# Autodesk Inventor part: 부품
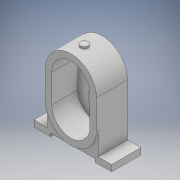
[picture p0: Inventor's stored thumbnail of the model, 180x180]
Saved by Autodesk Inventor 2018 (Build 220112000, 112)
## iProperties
Created: 2021-05
Part Number: 부품
Material: 일반
Document SubType Name: Modeling
Designer: admin
Density: 1 g/cm^3
Appearance: 기본값
Author: admin
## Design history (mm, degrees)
sketch "스케치1"
  geometry: L1 (85.4, 0)-(-85.4, 0) reference; L2 (0, -74.9)-(0, 109.9) reference; L3 (40, 43.5)-(40, -38.5); L4 (40, -38.5)-(61, -38.5); L5 (61, -38.5)-(61, -48.5); L6 (61, -48.5)-(35, -48.5); L7 (35, -48.5)-(35, -43.5); L8 (35, -43.5)-(0, -43.5); L9 (-40, 43.5)-(-40, -38.5); L10 (-40, -38.5)-(-61, -38.5); L11 (-61, -38.5)-(-61, -48.5); L12 (-61, -48.5)-(-35, -48.5); L13 (-35, -48.5)-(-35, -43.5); L14 (-35, -43.5)-(0, -43.5); L15 (40, 43.5)-(-40, 43.5); A1 r 40 centre (0, 43.5) between (40, 43.5) and (-40, 43.5); 1 further point
  constraints: 26 end point, 6 symmetric about line, 5 perpendicular, 2 point on circle, 1 centre point, 1 horizontal, 1 midpoint, 1 point on line, 1 vertical, 1 other
  dimensions: "d0" = 70 distance between parallel lines of L13 L7; "d1" = 10 distance between parallel lines of L6 L4; "d2" = 122 distance between parallel lines of L11 L5; "d4" = 5 distance of L12.end L13.end; "d5" = 80 distance of L3.start L9.start; "d6" = 92 distance between parallel lines of L12 L15
extrude "돌출1" new body sketch "스케치1" stored distance "d7" = 46; taper "d8" = 0 deg
sketch "스케치2"
  geometry: L1 (40, -43.5)-(40, 38.5) reference; L2 (40, 38.5)-(61, 38.5) reference; L3 (61, 38.5)-(61, 48.5) reference; L4 (61, 48.5)-(35, 48.5) reference; L5 (35, 48.5)-(35, 43.5) reference; L6 (35, 43.5)-(-35, 43.5) reference; L7 (-35, 43.5)-(-35, 48.5) reference; L8 (-35, 48.5)-(-61, 48.5) reference; L9 (-61, 48.5)-(-61, 38.5) reference; L10 (-61, 38.5)-(-40, 38.5) reference; L11 (-40, 38.5)-(-40, -43.5) reference; L12 (-85.4, 0)-(85.4, 0) reference; L13 (0, 74.9)-(0, -109.9) reference; L14 (0, 1.5)-(0, -43.5); L15 (26, 1.5)-(26, -43.5); L16 (-26, -43.5)-(-26, 1.5); A1 r 40 centre (0, -43.5) between (-40, -43.5) and (40, -43.5) reference; A2 r 26 centre (0, 1.5) between (26, 1.5) and (-26, 1.5); A3 r 26 centre (0, -43.5) between (-26, -43.5) and (26, -43.5); 2 further points
  constraints: 8 end point, 4 point on circle, 4 tangent, 2 centre point, 2 point on line, 1 coincident, 1 midpoint, 1 parallel
  dimensions: "d9" = 26 radius of A3; "d11" = 45 distance of L14.start A1.centre
extrude "돌출2" join sketch "스케치2" distance "d12" = 8; taper "d13" = 0 deg
sketch "스케치3"
  geometry: L1 (26, -43.5)-(26, 1.5) reference; L2 (-26, 1.5)-(-26, -43.5) reference; L3 (-85.4, 0)-(85.4, 0) reference; L4 (0, 74.9)-(0, -109.9) reference; L5 (26, -43.5)-(26, 1.5) reference; L6 (26, -13.5)-(-26, -13.5); L7 (-26, -13.5)-(-26, 1.5); L8 (-26, 1.5)-(26, 1.5); L9 (26, 1.5)-(26, -13.5); A1 r 26 centre (0, 1.5) between (26, 1.5) and (-26, 1.5) reference; A2 r 26 centre (0, -43.5) between (-26, -43.5) and (26, -43.5) reference; A3 r 26 centre (0, 1.5) between (26, 1.5) and (-26, 1.5); 1 further point
  constraints: 8 end point, 2 parallel, 2 point on circle, 1 centre point, 1 coincident, 1 horizontal, 1 perpendicular, 1 point on line
  dimensions: "d14" = 30 distance from line of L6 A2.centre
extrude "돌출3" join sketch "스케치3" distance "d15" = 3; taper "d16" = 0 deg
sketch "스케치4"
  geometry: L1 (-40, 43.5)-(-40, -38.5) reference; L2 (-40, -38.5)-(-61, -38.5) reference; L3 (-61, -38.5)-(-61, -48.5) reference; L4 (-61, -48.5)-(-35, -48.5) reference; L5 (-35, -48.5)-(-35, -43.5) reference; L6 (-35, -43.5)-(35, -43.5) reference; L7 (35, -43.5)-(35, -48.5) reference; L8 (35, -48.5)-(61, -48.5) reference; L9 (61, -48.5)-(61, -38.5) reference; L10 (61, -38.5)-(40, -38.5) reference; L11 (40, -38.5)-(40, 43.5) reference; L12 (-85.4, 0)-(85.4, 0) reference; L13 (0, -74.9)-(0, 109.9) reference; L14 (0, 43.5)-(0, -1.5); L15 (-40, 43.5)-(-40, -1.5); L16 (40, -1.5)-(40, 43.5); A1 r 40 centre (0, 43.5) between (40, 43.5) and (-40, 43.5) reference; A2 r 40 centre (0, 43.5) between (40, 43.5) and (-40, 43.5); A3 r 40 centre (0, -1.5) between (-40, -1.5) and (40, -1.5); 2 further points
  constraints: 8 end point, 4 point on circle, 4 tangent, 2 centre point, 1 concentric, 1 midpoint, 1 parallel, 1 point on line
  dimensions: "d17" = 45 distance of L14.end L14.start
extrude "돌출4" join sketch "스케치4" distance "d18" = 3; taper "d19" = 0 deg
sketch "스케치5"
  geometry: L1 (-40, 43.5)-(-40, -1.5) reference; L2 (40, -1.5)-(40, 43.5) reference; L3 (0, -74.9)-(0, 109.9) reference; L4 (-85.4, 0)-(85.4, 0) reference; L5 (0, -1.5)-(0, 43.5); L6 (30, -1.5)-(30, 43.5); L7 (-30, 43.5)-(-30, -1.5); A1 r 40 centre (0, -1.5) between (-40, -1.5) and (40, -1.5) reference; A2 r 40 centre (0, 43.5) between (40, 43.5) and (-40, 43.5) reference; A3 r 30 centre (0, -1.5) between (-30, -1.5) and (30, -1.5); A4 r 30 centre (0, 43.5) between (30, 43.5) and (-30, 43.5); 2 further points
  constraints: 8 end point, 4 point on circle, 4 tangent, 2 centre point, 1 midpoint, 1 parallel, 1 perpendicular
  dimensions: "d20" = 30 radius of A4
extrude "돌출5" cut sketch "스케치5" distance "d21" = 41; taper "d22" = 0 deg
sketch "스케치6"
  geometry: L1 (30, 43.5)-(30, -1.5) reference; L2 (-30, -1.5)-(-30, 43.5) reference; L3 (-85.4, 0)-(85.4, 0) reference; L4 (0, -74.9)-(0, 109.9) reference; C1 r 14 at (0, 43.5); C2 r 14 at (0, -1.5); A1 r 30 centre (0, 43.5) between (30, 43.5) and (-30, 43.5) reference; A2 r 30 centre (0, -1.5) between (-30, -1.5) and (30, -1.5) reference; 1 further point
  constraints: 2 centre point, 2 coincident
  dimensions: "d23" = 28 diameter of C1; "d24" = 28 diameter of C2
extrude "돌출6" cut sketch "스케치6" distance "d25" = 8; taper "d26" = 0 deg
sketch "스케치7"
  geometry: C1 r 14 at (0, 0) reference; C2 r 11 at (0, 0); 1 further point
  constraints: 1 centre point, 1 coincident
  dimensions: "d27" = 22 diameter of C2
extrude "돌출7" cut sketch "스케치7" distance "d28" = 4; taper "d29" = 0 deg
sketch "스케치8"
  geometry: L1 (26, -13.5)-(-26, -13.5) reference; L2 (-26, -13.5)-(-26, -43.5) reference; L3 (26, -43.5)-(26, -13.5) reference; C1 r 14 at (0, -43.5); A1 r 26 centre (0, -43.5) between (-26, -43.5) and (26, -43.5) reference; 1 further point
  constraints: 1 centre point, 1 coincident
  dimensions: "d30" = 28 diameter of C1
extrude "돌출8" cut sketch "스케치8" distance "d31" = 4; taper "d32" = 0 deg
sketch "스케치9"
  geometry: L1 (23, -15.5)-(23, 12.5) reference; L2 (15, -15.5)-(15, 12.5) reference; L3 (23, -1.5)-(23, -1.5) reference; L4 (23, -1.5)-(34, -1.5) reference; L5 (34, -1.5)-(34, -1.5) reference; L6 (23, -1.5)-(34, -1.5) reference; L7 (23, 43.5)-(-26, 43.5) reference; L8 (23, -38.5)-(23, 43.5) reference; L9 (-23, -38.5)-(23, -38.5) reference; L10 (-23, -1.5)-(-23, -38.5) reference; L11 (-23, -1.5)-(-26, -1.5) reference; L12 (-26, 43.5)-(-26, -1.5) reference; L13 (0, -74.9)-(0, 109.9) reference; L14 (15, 12.5)-(23, 12.5) reference; L15 (15, -15.5)-(23, -15.5) reference; L16 (-26, -1.5)-(15, -1.5) reference; L17 (0, -1.5)-(23, -1.5); L18 (23, -1.5)-(34, -1.5) reference; L19 (23, -1.5)-(27, -1.5); L20 (27, -1.5)-(27, 5.5); L21 (24, 8.5)-(23, 8.5); L22 (23, 8.5)-(23, -1.5); A1 r 3 centre (24, 5.5) between (27, 5.5) and (24, 8.5); 2 further points
  constraints: 10 end point, 4 point on line, 2 parallel, 2 point on circle, 2 tangent, 1 centre point, 1 collinear, 1 horizontal, 1 perpendicular
  dimensions: "d34" = 4 distance of point (27, 8.5) L21.end; "d35" = 20 diameter of L21 L17; "d36" = 3 radius of A1
revolve "회전1" sketch "스케치9" stored, may be unused: angle "d37" = 90 deg
node "작업 평면1"
sketch "스케치10"
  geometry: L1 (-120.4, -23)-(50.4, -23) reference; L2 (-35, -61)-(-35, 23) reference; L3 (-75, -49)-(5, -49) reference; C1 r 6 at (-35, -28); 1 further point
  constraints: 1 centre point, 1 point on line
  dimensions: "d39" = 21 distance from line of L3 C1.centre; "d40" = 12 diameter of C1
extrude "돌출9" join sketch "스케치10" stored distance "d41" = 4; taper "d42" = 0 deg
node "솔리드1"
node "투영된 루프1"
node "투영된 루프2"
node "투영된 루프3"
node "투영된 루프4"
node "투영된 루프5"
node "투영된 루프6"
node "투영된 루프7"
node "투영된 루프8"
node "투영된 루프9"
node "투영된 루프10"
